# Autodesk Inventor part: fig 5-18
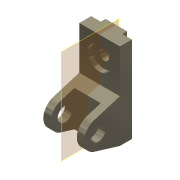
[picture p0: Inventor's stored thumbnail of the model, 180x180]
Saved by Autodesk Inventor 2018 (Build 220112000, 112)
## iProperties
Shininess: 65.0
Angle Display Precision: 2
Document Length Units: 11269
Document Angle Units: 11279
Document Time Units: 11290
Document Mass Units: 11283
Document Length Units Precision: 3
Document Angle Units Precision: 2
Compacted: False
Created: 2001-11
Part Number: fig 5-18
Document SubType Name: Modeling
Designer: Renu Muthoo
Density: 1 g/cm^3
Material: Generic
Appearance: Metal-Titanium (Polished)
Density: 0.0
Volumn: 0.0
Area: 0.0
PropertySet Name: Model Information
Control State: 0
Master: False
Checked Out: False
Author: Renu Muthoo
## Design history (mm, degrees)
node "Sketch1"
sketch "Sketch2"
  geometry: L1 (33.257, 104.664)-(33.257, -75.336); L2 (33.257, -75.336)-(8.257, -75.336); L3 (8.257, -75.336)-(-45.451, -59.045); L4 (-45.451, -1.628)-(8.257, 14.664); L5 (8.257, 14.664)-(8.257, 104.664); L6 (8.257, 104.664)-(33.257, 104.664); C1 r 15 at (-36.743, -30.336); A1 r 30 centre (-36.743, -30.336) between (-45.451, -1.628) and (-45.451, -59.045)
  constraints: 12 end point, 2 centre point, 2 equal length, 2 parallel, 2 point on circle, 2 tangent, 1 coincident, 1 perpendicular, 1 vertical
  dimensions: "d0" = 180 distance of L1.start L1.end; "d1" = 30 radius of A1; "d2" = 25 distance of L5.end L1.start; "d3" = 45 distance from line of L2 A1.centre; "d4" = 70 distance from line of L1 A1.centre; "d5" = 30 diameter of C1
extrude "Extrusion1" new body sketch "Sketch2" distance "d6" = 85; taper "d7" = 0 deg
workplane "Work Plane1"
sketch "Sketch3"
  geometry: L1 (15, 62.364)-(70, 62.364); L2 (70, 62.364)-(70, -52.386); L3 (70, -52.386)-(15, -52.386); L4 (15, -52.386)-(15, 62.364); L5 (0, -45)-(0, -28.708) reference
  constraints: 8 end point, 2 parallel, 1 horizontal, 1 perpendicular
  dimensions: "d8" = 55 distance of L1.start L1.end; "d9" = 15 distance between parallel lines of L5 L4
extrude "Extrusion2" cut sketch "Sketch3" distance "d10" = 50; taper "d11" = 0 deg
sketch "Sketch4"
  geometry: L1 (0, 25)-(85, 25) reference; L2 (0, 0)-(0, 25) reference; L3 (20, 25)-(65, 25); L4 (65, 25)-(65, 35); L5 (65, 35)-(20, 35); L6 (20, 35)-(20, 25)
  constraints: 8 end point, 2 parallel, 1 horizontal, 1 perpendicular, 1 point on line
  dimensions: "d12" = 45 distance of L4.end L5.end; "d13" = 10 distance of L3.end L4.end; "d14" = 20 distance between parallel lines of L2 L6
extrude "Extrusion3" join sketch "Sketch4" stored distance "d15" = 50; taper "d16" = 0 deg
sketch "Sketch5"
  geometry: L1 (85, 0)-(85, 90) reference; L2 (0, 90)-(85, 90) reference; 1 further point
  dimensions: "d17" = 42 distance from line of L2 point (42.5, 48); "d18" = 42.5 distance from line of L1 point (42.5, 48)
hole "Hole1" sketch "Sketch5" at (42.5, 48) diameter "d19" = 20; stored, may be unused: countersink angle "d23" = 82 deg, drill point angle "d25" = 118 deg; dims "d20" = 6, "d21" = 50, "d22" = 10, "d24" = 8
workplane "Work Plane9"
body "Solid1"
